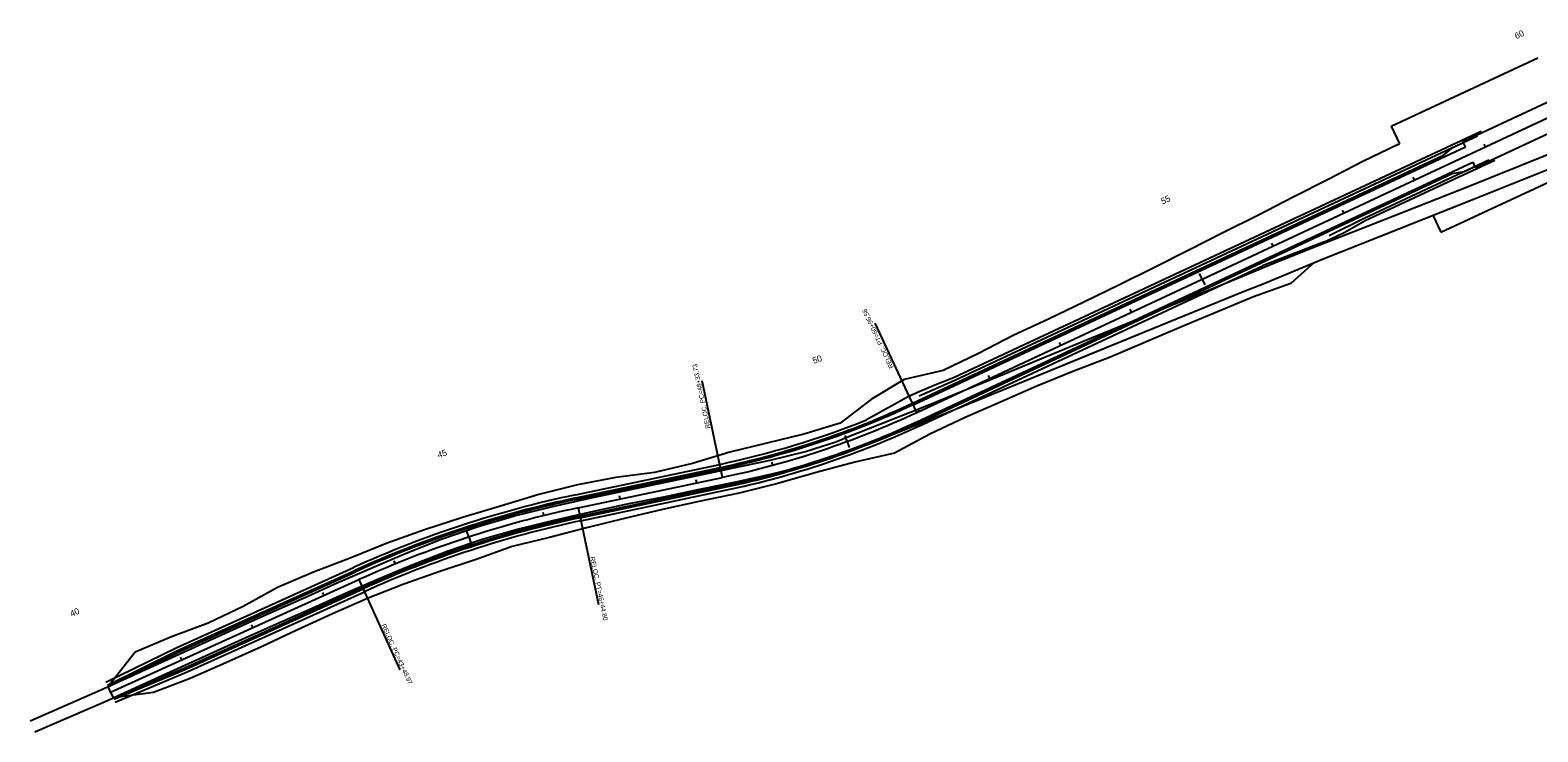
# Model space of a CAD drawing. Extents: x 1965724 to 1970311, y 1117080 to 1118208.
# Drawn here: x 1965724 to 1967654, y 1117080 to 1117979 of the extents above; entities that cross this region are included whole.
import ezdxf

# ---------------------------------------------------------------- set-up
doc = ezdxf.new("R2010")
doc.units = 0
for name, color, linetype in [('RD_EX_Road', 7, 'Continuous'), ('RD_EX_RW', 7, 'Continuous'), ('RD_HC_CL_Rel', 7, 'Continuous'), ('RD_HC_Data_Rel', 7, 'Continuous'), ('RD_HC_Data_Tic_Rel', 7, 'Continuous'), ('RD_HC_TX_Rel_Sta50', 7, 'Continuous'), ('RD_PD_Bridge', 7, 'Continuous'), ('RD_PD_EarthShd', 7, 'Continuous'), ('RD_PD_Final_TrvlWay', 7, 'Continuous'), ('RD_PD_PaveShd', 7, 'Continuous'), ('RD_PD_RW', 7, 'Continuous'), ('RD_Sketch3', 7, 'Continuous'), ('RD_Sketch4', 7, 'Continuous')]:
    doc.layers.add(name, color=color, linetype=linetype)

msp = doc.modelspace()

# ---------------------------------------------------------------- linework, layer by layer
at = {"layer": 'RD_EX_Road'}
for points in [[(1966769.5, 1117457.5), (1966870.2, 1117497.3), (1966971.2, 1117539), (1967071.1, 1117580.2), (1967172.6, 1117621.5), (1967270.8, 1117661.7), (1967321.1, 1117682.6), (1967371.5, 1117702.9), (1967470.3, 1117741.6), (1967566.7, 1117779.5), (1967661.2, 1117817.5), (1967694.4, 1117831.2)], [(1967302.2, 1117654.1), (1967379.3, 1117686.2), (1967476.1, 1117724.4), (1967573.9, 1117763.5), (1967667.7, 1117800.7), (1967701.6, 1117814)], [(1966775.8, 1117440.6), (1966876.2, 1117480.4), (1966978.5, 1117522.1), (1967078.3, 1117563.1), (1967180.7, 1117605.1), (1967278, 1117644.7), (1967302.2, 1117654.1)], [(1965723.8, 1117094.5), (1965813.3, 1117133.7), (1965900.5, 1117173.5), (1965988.5, 1117213.4), (1966031.8, 1117233), (1966074.7, 1117252.1), (1966117.8, 1117271.6), (1966161.1, 1117290.5), (1966205.4, 1117309.2), (1966251.2, 1117327.4), (1966297.2, 1117343.1), (1966344.1, 1117357), (1966390.8, 1117368.6), (1966438.1, 1117379.1), (1966484.5, 1117389.1), (1966531.2, 1117398.7), (1966578.4, 1117408.6), (1966604.5, 1117414.1), (1966624.5, 1117418.3), (1966671.3, 1117428.3), (1966716.5, 1117439.3), (1966736.6, 1117445.6), (1966754.1, 1117451.4), (1966759.7, 1117453.5), (1966769.5, 1117457.5)], [(1965730, 1117080.3), (1965819.8, 1117119.1), (1965907.7, 1117159.3), (1965995.4, 1117199), (1966039.3, 1117218.5), (1966081.2, 1117237.1), (1966124.7, 1117256.6), (1966167.7, 1117275.6), (1966211.5, 1117293.6), (1966257.8, 1117311.6), (1966302.7, 1117327.2), (1966347.9, 1117340), (1966394.8, 1117351.6), (1966441.6, 1117361.9), (1966488.6, 1117372.1), (1966534.9, 1117381.3), (1966581.2, 1117390.9), (1966629.5, 1117400.9), (1966675.6, 1117411.1), (1966721.7, 1117422.8), (1966766.8, 1117439), (1966775.8, 1117440.6)]]:
    msp.add_lwpolyline(points, dxfattribs=at)
at = {"layer": 'RD_EX_RW'}
for points in [[(1966769.5, 1117457.5), (1966870.2, 1117497.3), (1966971.2, 1117539), (1967071.1, 1117580.2), (1967172.6, 1117621.5), (1967270.8, 1117661.7), (1967321.1, 1117682.6), (1967371.5, 1117702.9), (1967470.3, 1117741.6), (1967566.7, 1117779.5), (1967661.2, 1117817.5), (1967694.6, 1117831.3)], [(1967302.2, 1117654.1), (1967379.3, 1117686.2), (1967476.1, 1117724.4), (1967573.9, 1117763.5), (1967667.7, 1117800.7), (1967701.6, 1117814)], [(1966775.8, 1117440.6), (1966876.2, 1117480.4), (1966978.5, 1117522.1), (1967180.7, 1117605.1), (1967278, 1117644.7), (1967302.2, 1117654.1)], [(1965723.8, 1117094.5), (1965813.3, 1117133.7), (1965900.5, 1117173.5), (1965988.5, 1117213.4), (1966031.8, 1117233), (1966074.7, 1117252.1), (1966117.8, 1117271.6), (1966161.1, 1117290.5), (1966205.4, 1117309.2), (1966251.2, 1117327.4), (1966297.2, 1117343.1), (1966344.1, 1117357), (1966390.8, 1117368.6), (1966438.1, 1117379.1), (1966484.5, 1117389.1), (1966531.2, 1117398.7), (1966578.4, 1117408.6), (1966604.5, 1117414.1), (1966624.5, 1117418.3), (1966671.3, 1117428.3), (1966716.5, 1117439.3), (1966736.6, 1117445.6), (1966754.1, 1117451.4), (1966759.7, 1117453.5), (1966769.5, 1117457.5)], [(1965730, 1117080.3), (1965819.8, 1117119.1), (1965907.7, 1117159.3), (1965995.4, 1117199), (1966039.3, 1117218.5), (1966081.2, 1117237.1), (1966124.7, 1117256.6), (1966167.7, 1117275.6), (1966211.5, 1117293.6), (1966257.8, 1117311.6), (1966302.7, 1117327.2), (1966347.9, 1117340), (1966394.8, 1117351.6), (1966441.6, 1117361.9), (1966488.6, 1117372.1), (1966534.9, 1117381.3), (1966581.2, 1117390.9), (1966629.5, 1117400.9), (1966675.6, 1117411.1), (1966721.7, 1117422.8), (1966766.8, 1117439), (1966775.8, 1117440.6)]]:
    msp.add_lwpolyline(points, dxfattribs=at)
at = {"layer": 'RD_HC_CL_Rel'}
for p, q in [((1966858.9, 1117489.3), (1967685.7, 1117875.7)), ((1966425.3, 1117367.2), (1966610.1, 1117406.2)), ((1965826.9, 1117131.2), (1966144.7, 1117275.3))]:
    msp.add_line(p, q, dxfattribs=at)
for centre, radius, start, end in [((1966373.7, 1118527.5), 1145.9, 281.9047, 295.0463), ((1966705.5, 1116038), 1358.4, 101.9047, 114.3826)]:
    msp.add_arc(centre, radius, start, end, dxfattribs=at)
at = {"layer": 'RD_HC_Data_Rel'}
for p, q in [((1966858.9, 1117489.3), (1966805.4, 1117603.8)), ((1966610.1, 1117406.2), (1966584, 1117529.9)), ((1966425.3, 1117367.2), (1966451.3, 1117243.6)), ((1966144.7, 1117275.3), (1966197, 1117159.9))]:
    msp.add_line(p, q, dxfattribs=at)
at = {"layer": 'RD_HC_Data_Tic_Rel'}
for p, q in [((1967586.8, 1117829.4), (1967585.1, 1117833.1)), ((1967496.2, 1117787.1), (1967494.5, 1117790.7)), ((1967405.6, 1117744.8), (1967403.9, 1117748.4)), ((1967315, 1117702.4), (1967313.3, 1117706.1)), ((1967224.4, 1117660.1), (1967221, 1117667.3)), ((1967224.4, 1117660.1), (1967227.8, 1117652.8)), ((1967133.8, 1117617.8), (1967132.1, 1117621.4)), ((1967043.2, 1117575.4), (1967041.5, 1117579)), ((1966952.6, 1117533.1), (1966950.9, 1117536.7)), ((1966862, 1117490.8), (1966860.3, 1117494.4)), ((1966769.8, 1117452.2), (1966767, 1117459.7)), ((1966769.8, 1117452.2), (1966772.5, 1117444.6)), ((1966674.5, 1117421.7), (1966673.5, 1117425.6)), ((1966577.1, 1117399.2), (1966576.3, 1117403.1)), ((1966479.3, 1117378.6), (1966478.4, 1117382.5)), ((1966381.6, 1117357.3), (1966380.6, 1117361.1)), ((1966285.4, 1117329.9), (1966283, 1117337.5)), ((1966285.4, 1117329.9), (1966287.9, 1117322.2)), ((1966191.6, 1117295.5), (1966190, 1117299.2)), ((1966100.1, 1117255.1), (1966098.4, 1117258.7)), ((1966009, 1117213.8), (1966007.4, 1117217.4)), ((1965917.9, 1117172.5), (1965916.3, 1117176.1)), ((1965826.9, 1117131.2), (1965823.5, 1117138.5)), ((1965826.9, 1117131.2), (1965830.2, 1117123.9))]:
    msp.add_line(p, q, dxfattribs=at)
at = {"layer": 'RD_PD_Bridge'}
for p, q in [((1967576.2, 1117844.9), (1967677.9, 1117892.4)), ((1967591.9, 1117811.4), (1967693.5, 1117858.9))]:
    msp.add_line(p, q, dxfattribs=at)
at = {"layer": 'RD_PD_EarthShd'}
for p, q in [((1966906.1, 1117534), (1967581.4, 1117849.6)), ((1967546.3, 1117787.9), (1967598.8, 1117812.4)), ((1967433, 1117735), (1967546.3, 1117787.9)), ((1967406.8, 1117720.4), (1967433, 1117735)), ((1967379.7, 1117707.3), (1967301.3, 1117677.3)), ((1967379.7, 1117707.3), (1967388.9, 1117711.6)), ((1967388.9, 1117711.6), (1967406.8, 1117720.4)), ((1966866.1, 1117473.9), (1967301.3, 1117677.3)), ((1966877.9, 1117523.2), (1966906, 1117533.9)), ((1966850.7, 1117510.9), (1966859.8, 1117515.1)), ((1966859.7, 1117515.1), (1966878, 1117523.2)), ((1966850.7, 1117510.9), (1966794.4, 1117479.8)), ((1966421.8, 1117383.8), (1966606.6, 1117422.8)), ((1966428.8, 1117350.6), (1966613.6, 1117389.6)), ((1965910.8, 1117187.9), (1966137.7, 1117290.8)), ((1965924.9, 1117157), (1966151.7, 1117259.8)), ((1965820.9, 1117143.8), (1965910.8, 1117187.9)), ((1965832.5, 1117118.3), (1965924.9, 1117157))]:
    msp.add_line(p, q, dxfattribs=at)
for centre, radius, start, end in [((1966373.7, 1118527.5), 1128.9, 281.9047, 291.8776), ((1966373.7, 1118527.5), 1162.9, 281.9047, 295.0463), ((1966705.5, 1116038), 1375.4, 101.9047, 114.3826), ((1966705.5, 1116038), 1341.4, 101.9047, 114.3826)]:
    msp.add_arc(centre, radius, start, end, dxfattribs=at)
at = {"layer": 'RD_PD_Final_TrvlWay'}
for p, q in [((1967558.1, 1117836.5), (1967576.2, 1117844.9)), ((1966854.2, 1117499.3), (1967561.3, 1117829.7)), ((1967561.3, 1117829.7), (1967558.1, 1117836.5)), ((1966863.5, 1117479.3), (1967570.6, 1117809.7)), ((1967570.6, 1117809.7), (1967573.7, 1117802.9)), ((1967591.9, 1117811.4), (1967573.7, 1117802.9)), ((1966423, 1117378), (1966607.9, 1117417)), ((1966427.5, 1117356.5), (1966612.4, 1117395.4)), ((1965913.4, 1117182.5), (1966140.2, 1117285.3)), ((1965922.5, 1117162.5), (1966149.2, 1117265.3)), ((1965823.2, 1117138.2), (1965913.4, 1117182.5)), ((1965830.2, 1117123.9), (1965922.5, 1117162.5))]:
    msp.add_line(p, q, dxfattribs=at)
for centre, radius, start, end in [((1966373.7, 1118527.5), 1134.9, 281.9047, 295.0463), ((1966373.7, 1118527.5), 1156.9, 281.9047, 295.0463), ((1966705.5, 1116038), 1369.4, 101.9047, 114.3826), ((1966705.5, 1116038), 1347.4, 101.9047, 114.3826)]:
    msp.add_arc(centre, radius, start, end, dxfattribs=at)
at = {"layer": 'RD_PD_PaveShd'}
for p, q in [((1967533.2, 1117818.8), (1967545.1, 1117828.7)), ((1967545.1, 1117828.7), (1967558.7, 1117835.1)), ((1966853.4, 1117501.1), (1967533.2, 1117818.8)), ((1967559.5, 1117797.9), (1967573.1, 1117804.3)), ((1966864.4, 1117477.5), (1967544.2, 1117795.2)), ((1967544.2, 1117795.2), (1967559.5, 1117797.9)), ((1966422.6, 1117379.9), (1966607.4, 1117418.9)), ((1966427.9, 1117354.5), (1966612.8, 1117393.5)), ((1965912.5, 1117184.3), (1966139.3, 1117287.1)), ((1965923.3, 1117160.6), (1966150.1, 1117263.4)), ((1965822.7, 1117140.2), (1965912.5, 1117184.3)), ((1965830.9, 1117122), (1965923.3, 1117160.6))]:
    msp.add_line(p, q, dxfattribs=at)
for centre, radius, start, end in [((1966373.7, 1118527.5), 1132.9, 281.9047, 295.0463), ((1966373.7, 1118527.5), 1158.9, 281.9047, 295.0463), ((1966705.5, 1116038), 1371.4, 101.9047, 114.3826), ((1966705.5, 1116038), 1345.4, 101.9047, 114.3826)]:
    msp.add_arc(centre, radius, start, end, dxfattribs=at)
at = {"layer": 'RD_PD_RW'}
for p, q in [((1967466.2, 1117855.9), (1967654, 1117943.6)), ((1967466.2, 1117855.9), (1967476.8, 1117833.3)), ((1967475, 1117832.4), (1967430, 1117810.6)), ((1967475, 1117832.4), (1967476.8, 1117833.3)), ((1967430, 1117810.6), (1967385.5, 1117787.6)), ((1967529.7, 1117720), (1967717.5, 1117807.7)), ((1967385.5, 1117787.6), (1967340.9, 1117765)), ((1967340.9, 1117765), (1967296.4, 1117742.1)), ((1967296.4, 1117742.1), (1967251.7, 1117719.7)), ((1967519.5, 1117741.8), (1967529.7, 1117720)), ((1967251.7, 1117719.7), (1967207.1, 1117697.1)), ((1967207.1, 1117697.1), (1967162.4, 1117674.5)), ((1967162.4, 1117674.5), (1967117.5, 1117652.5)), ((1967367.7, 1117681.4), (1967337.6, 1117654.3)), ((1967117.5, 1117652.5), (1967072.6, 1117630.4)), ((1967337.6, 1117654.3), (1967290.1, 1117637.3)), ((1967072.6, 1117630.4), (1967027.5, 1117609)), ((1967290.1, 1117637.3), (1967243.8, 1117618.3)), ((1967243.8, 1117618.3), (1967197.6, 1117599.1)), ((1967027.5, 1117609), (1966982.2, 1117587.8)), ((1967197.6, 1117599.1), (1967151.6, 1117579.5)), ((1966982.2, 1117587.8), (1966937.7, 1117564.8)), ((1967151.6, 1117579.5), (1967105.6, 1117559.8)), ((1966937.7, 1117564.8), (1966892.8, 1117543.2)), ((1967105.6, 1117559.8), (1967058.8, 1117541.9)), ((1966892.8, 1117543.2), (1966842.9, 1117531.7)), ((1967058.8, 1117541.9), (1967012.5, 1117522.9)), ((1966842.9, 1117531.7), (1966801.1, 1117506.3)), ((1967012.5, 1117522.9), (1966966.7, 1117502.9)), ((1966801.1, 1117506.3), (1966761, 1117475.6)), ((1966966.7, 1117502.9), (1966920.9, 1117482.7)), ((1966761, 1117475.6), (1966714.3, 1117461.6)), ((1966920.9, 1117482.7), (1966875.7, 1117461.6)), ((1966714.3, 1117461.6), (1966666.9, 1117449.8)), ((1966875.7, 1117461.6), (1966830.2, 1117437.3)), ((1966619.5, 1117438.3), (1966571.8, 1117424.1)), ((1966666.9, 1117449.8), (1966619.5, 1117438.3)), ((1966830.2, 1117437.3), (1966779.4, 1117425.6)), ((1966571.8, 1117424.1), (1966523.3, 1117412.5)), ((1966779.4, 1117425.6), (1966730, 1117412.4)), ((1966473.5, 1117406.2), (1966424.4, 1117396.5)), ((1966523.3, 1117412.5), (1966473.5, 1117406.2)), ((1966680.9, 1117398.2), (1966631.4, 1117386)), ((1966730, 1117412.4), (1966680.9, 1117398.2)), ((1966374.9, 1117384.3), (1966326.1, 1117369.4)), ((1966424.4, 1117396.5), (1966374.9, 1117384.3)), ((1966631.4, 1117386), (1966582.1, 1117375.9)), ((1966326.1, 1117369.4), (1966277.3, 1117354.8)), ((1966533.3, 1117365), (1966484.6, 1117353.4)), ((1966582.1, 1117375.9), (1966533.3, 1117365)), ((1966277.3, 1117354.8), (1966228.8, 1117339.1)), ((1966436.1, 1117341.4), (1966388.5, 1117329.3)), ((1966484.6, 1117353.4), (1966436.1, 1117341.4)), ((1966180.8, 1117321.9), (1966133.4, 1117302.8)), ((1966228.8, 1117339.1), (1966180.8, 1117321.9)), ((1966388.5, 1117329.3), (1966340.9, 1117317.6)), ((1966133.4, 1117302.8), (1966086.7, 1117284.8)), ((1966340.9, 1117317.6), (1966294.8, 1117301.1)), ((1966086.7, 1117284.8), (1966040.6, 1117265.1)), ((1966248.3, 1117285.8), (1966202.1, 1117269.5)), ((1966294.8, 1117301.1), (1966248.3, 1117285.8)), ((1966040.6, 1117265.1), (1965996.7, 1117240.8)), ((1966202.1, 1117269.5), (1966156.5, 1117251.5)), ((1966156.5, 1117251.5), (1966110.7, 1117231.6)), ((1965996.7, 1117240.8), (1965951.6, 1117219.5)), ((1966110.7, 1117231.6), (1966065.3, 1117210.7)), ((1965951.6, 1117219.5), (1965904.7, 1117201.9)), ((1966065.3, 1117210.7), (1966020.2, 1117189.2)), ((1965904.7, 1117201.9), (1965858.4, 1117182.2)), ((1966020.2, 1117189.2), (1965974.5, 1117168.9)), ((1965858.4, 1117182.2), (1965823.6, 1117138.4)), ((1965974.5, 1117168.9), (1965928.6, 1117148.8)), ((1965928.6, 1117148.8), (1965881.8, 1117130.7)), ((1965881.8, 1117130.7), (1965830.2, 1117123.9))]:
    msp.add_line(p, q, dxfattribs=at)
at = {"layer": 'RD_Sketch3'}
for p, q in [((1967544.8, 1117791.1), (1967591.2, 1117812.8)), ((1967431.6, 1117738.1), (1967544.8, 1117791.1)), ((1967386.7, 1117716.1), (1967431.6, 1117738.1))]:
    msp.add_line(p, q, dxfattribs=at)
at = {"layer": 'RD_Sketch4'}
for p, q in [((1966907.6, 1117530.8), (1967576.8, 1117843.6)), ((1967545.1, 1117828.7), (1967558.7, 1117835.1)), ((1966861.8, 1117510.5), (1966907.5, 1117530.8))]:
    msp.add_line(p, q, dxfattribs=at)

# ---------------------------------------------------------------- texts
at = {"layer": 'RD_HC_Data_Rel'}
for s, rotation, p in [('RELOC. PT=50+96.56', 115.0463, (1966829.5, 1117547.3)), ('RELOC. PC=48+33.73', 101.9047, (1966594.8, 1117469.4)), ('RELOC. PT=46+44.80', 281.9047, (1966440.6, 1117304)), ('RELOC. PC=43+48.97', 294.3826, (1966173.4, 1117216.9))]:
    msp.add_text(s, height=6, rotation=rotation, dxfattribs=at).set_placement(p)
at = {"layer": 'RD_HC_TX_Rel_Sta50'}
for s, rotation, p in [('60', 25.0463, (1967626.5, 1117967.2)), ('55', 25.0463, (1967173.7, 1117755.6)), ('50', 20.2184, (1966727.2, 1117551.5)), ('45', 18.0122, (1966246.8, 1117430.9)), ('40', 24.3826, (1965777.1, 1117227.3))]:
    msp.add_text(s, height=8, rotation=rotation, dxfattribs=at).set_placement(p)

doc.saveas('drawing.dxf')
